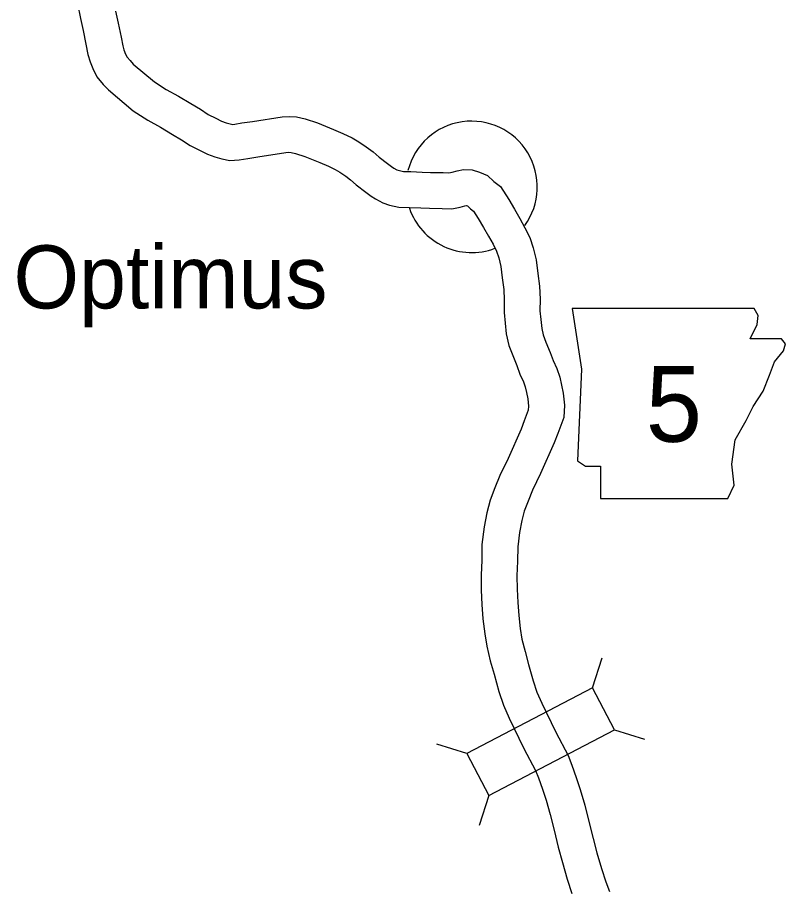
# Model space of a CAD drawing. Extents: x 1377389 to 1380723, y 1168351 to 1170484.
# Drawn here: x 1377801 to 1377865.3, y 1169750.4 to 1169823.5 of the extents above; entities that cross this region are included whole.
import ezdxf

# ---------------------------------------------------------------- set-up
doc = ezdxf.new("R2010")
doc.units = 0
doc.layers.add('B_Fill', color=7, linetype='Continuous')

msp = doc.modelspace()

# ---------------------------------------------------------------- linework, layer by layer
at = {"layer": 'B_Fill'}
for p, q in [((1377849.177, 1169767.377), (1377849.967, 1169769.896)), ((1377851.012, 1169763.868), (1377853.531, 1169763.078)), ((1377838.649, 1169761.873), (1377836.13, 1169762.662)), ((1377840.484, 1169758.364), (1377839.694, 1169755.844))]:
    msp.add_line(p, q, dxfattribs=at)
for points in [[(1377806.068, 1169824.632), (1377806.316, 1169823.399), (1377806.537, 1169822.396), (1377806.758, 1169821.254), (1377806.931, 1169820.376), (1377807.123, 1169819.753), (1377807.343, 1169819.207), (1377807.669, 1169818.514), (1377808.216, 1169817.882), (1377808.644, 1169817.41), (1377810.726, 1169815.654), (1377811.953, 1169814.879), (1377813.004, 1169814.289), (1377814.018, 1169813.684), (1377814.762, 1169813.251), (1377815.491, 1169812.757), (1377816.326, 1169812.337), (1377816.95, 1169812.047), (1377817.571, 1169811.808), (1377818.15, 1169811.657), (1377818.801, 1169811.519), (1377819.591, 1169811.551), (1377820.307, 1169811.689), (1377821.16, 1169811.814), (1377823.501, 1169812.182), (1377823.729, 1169812.193), (1377823.951, 1169812.176), (1377824.306, 1169812.096), (1377825.104, 1169811.834), (1377826.334, 1169811.33), (1377827.058, 1169811.029), (1377827.631, 1169810.76), (1377828.014, 1169810.527), (1377828.517, 1169810.194), (1377828.923, 1169809.894), (1377829.399, 1169809.475), (1377830.208, 1169808.845), (1377830.636, 1169808.535), (1377831.008, 1169808.293), (1377831.61, 1169807.973), (1377832.189, 1169807.778), (1377832.965, 1169807.597), (1377833.864, 1169807.579)], [(1377809.252, 1169824.017), (1377809.475, 1169823.004), (1377809.703, 1169821.829), (1377809.844, 1169821.109), (1377809.953, 1169820.756), (1377810.093, 1169820.407), (1377810.207, 1169820.166), (1377810.461, 1169819.872), (1377810.731, 1169819.575), (1377812.503, 1169818.08), (1377813.49, 1169817.457), (1377814.507, 1169816.886), (1377815.542, 1169816.269), (1377816.359, 1169815.792), (1377817.011, 1169815.351), (1377817.634, 1169815.038), (1377818.124, 1169814.81), (1377818.492, 1169814.668), (1377818.839, 1169814.577), (1377819.054, 1169814.532), (1377819.244, 1169814.54), (1377819.805, 1169814.648), (1377820.71, 1169814.78), (1377823.199, 1169815.172), (1377823.773, 1169815.198), (1377824.393, 1169815.151), (1377825.105, 1169814.992), (1377826.143, 1169814.65), (1377827.479, 1169814.103), (1377828.27, 1169813.773), (1377829.053, 1169813.407), (1377829.624, 1169813.059), (1377830.238, 1169812.652), (1377830.809, 1169812.23), (1377831.313, 1169811.787), (1377832.011, 1169811.244), (1377832.335, 1169811.008), (1377832.532, 1169810.88), (1377832.801, 1169810.737), (1377833.01, 1169810.667), (1377833.34, 1169810.59), (1377833.924, 1169810.578)], [(1377833.957, 1169810.577), (1377834.915, 1169810.537), (1377835.601, 1169810.512), (1377836.657, 1169810.503), (1377837.15, 1169810.483), (1377837.43, 1169810.54), (1377837.833, 1169810.64), (1377838.377, 1169810.747), (1377839.106, 1169810.722), (1377839.708, 1169810.54), (1377840.382, 1169810.259), (1377840.917, 1169809.744), (1377841.46, 1169809.32)], [(1377841.46, 1169809.32), (1377842.161, 1169808.249), (1377842.649, 1169807.423), (1377843.096, 1169806.643), (1377843.514, 1169805.876), (1377843.911, 1169805.051), (1377844.205, 1169804.197), (1377844.448, 1169803.191), (1377844.592, 1169802.062), (1377844.732, 1169800.98), (1377844.776, 1169799.906), (1377844.768, 1169798.94), (1377844.846, 1169798.195), (1377844.915, 1169797.455), (1377845.032, 1169796.907), (1377845.275, 1169796.314), (1377845.633, 1169795.427), (1377845.875, 1169794.77), (1377846.179, 1169794.09), (1377846.429, 1169793.389), (1377846.58, 1169792.697), (1377846.715, 1169792.028), (1377846.82, 1169791.038), (1377846.762, 1169790.009), (1377846.267, 1169788.666), (1377845.972, 1169787.888), (1377844.823, 1169785.316), (1377844.146, 1169783.909), (1377843.771, 1169783.005), (1377843.459, 1169782.174), (1377843.257, 1169781.372), (1377843.06, 1169780.386), (1377842.917, 1169779.183), (1377842.898, 1169777.976), (1377842.848, 1169776.754), (1377842.863, 1169775.642), (1377842.908, 1169774.525), (1377842.99, 1169773.432), (1377843.119, 1169772.33), (1377843.264, 1169771.454), (1377843.52, 1169770.406), (1377843.82, 1169769.322), (1377844.191, 1169767.966), (1377844.52, 1169767.014), (1377844.915, 1169766.1), (1377846.11, 1169763.661), (1377847.125, 1169761.718), (1377847.447, 1169760.917), (1377847.814, 1169759.883), (1377848.148, 1169758.879), (1377848.535, 1169757.548), (1377848.864, 1169756.195), (1377849.215, 1169754.778), (1377849.535, 1169753.577), (1377849.926, 1169752.247), (1377850.289, 1169751.148), (1377850.581, 1169750.335)], [(1377833.831, 1169807.58), (1377834.798, 1169807.539), (1377835.535, 1169807.512), (1377836.583, 1169807.504), (1377837.393, 1169807.47), (1377838.091, 1169807.613), (1377838.484, 1169807.71), (1377838.615, 1169807.736), (1377838.695, 1169807.712), (1377838.708, 1169807.707), (1377838.949, 1169807.475), (1377839.219, 1169807.264)], [(1377839.222, 1169807.261), (1377839.613, 1169806.664), (1377840.055, 1169805.915), (1377840.477, 1169805.179), (1377840.844, 1169804.506), (1377841.132, 1169803.909), (1377841.322, 1169803.355), (1377841.493, 1169802.648), (1377841.616, 1169801.68), (1377841.74, 1169800.725), (1377841.776, 1169799.856), (1377841.767, 1169798.796), (1377841.861, 1169797.901), (1377841.944, 1169797.002), (1377842.155, 1169796.016), (1377842.496, 1169795.183), (1377842.833, 1169794.348), (1377843.095, 1169793.637), (1377843.393, 1169792.972), (1377843.538, 1169792.562), (1377843.644, 1169792.08), (1377843.746, 1169791.572), (1377843.811, 1169790.963), (1377843.792, 1169790.626), (1377843.457, 1169789.717), (1377843.197, 1169789.033), (1377842.101, 1169786.578), (1377841.406, 1169785.134), (1377840.981, 1169784.107), (1377840.591, 1169783.07), (1377840.33, 1169782.033), (1377840.094, 1169780.858), (1377839.92, 1169779.384), (1377839.899, 1169778.062), (1377839.847, 1169776.794), (1377839.864, 1169775.56), (1377839.912, 1169774.353), (1377840.003, 1169773.146), (1377840.147, 1169771.91), (1377840.323, 1169770.851), (1377840.617, 1169769.649), (1377840.927, 1169768.526), (1377841.324, 1169767.079), (1377841.721, 1169765.928), (1377842.19, 1169764.844), (1377843.433, 1169762.306), (1377844.397, 1169760.461), (1377844.64, 1169759.857), (1377844.976, 1169758.908), (1377845.283, 1169757.986), (1377845.636, 1169756.774), (1377845.95, 1169755.48), (1377846.309, 1169754.031), (1377846.647, 1169752.767), (1377847.062, 1169751.354), (1377847.452, 1169750.17)]]:
    msp.add_lwpolyline(points, dxfattribs=at)
for points in [[(1377847.479, 1169799.134), (1377848.241, 1169794.059), (1377847.902, 1169786.361), (1377848.579, 1169785.938), (1377849.848, 1169785.938), (1377849.848, 1169783.231), (1377860.506, 1169783.231), (1377861.014, 1169784.331), (1377860.845, 1169786.107), (1377861.098, 1169788.138), (1377862.029, 1169789.745), (1377862.621, 1169790.929), (1377863.467, 1169792.198), (1377863.974, 1169793.551), (1377864.397, 1169794.651), (1377865.159, 1169795.582), (1377865.328, 1169796.174), (1377864.989, 1169796.597), (1377862.367, 1169796.597), (1377862.959, 1169797.781), (1377863.044, 1169798.542), (1377862.693, 1169799.127)], [(1377840.484, 1169758.364), (1377851.012, 1169763.868), (1377849.177, 1169767.377), (1377838.649, 1169761.873)]]:
    msp.add_lwpolyline(points, close=True, dxfattribs=at)
for start, end in [(323.91026, 165.51389), (198.96543, 290.77226)]:
    msp.add_arc((1377839.05, 1169809.302), 5.5, start, end, dxfattribs=at)

# ---------------------------------------------------------------- texts
for s, height, p in [('Optimus', 5.28, (1377800.702, 1169799.127)), ('5', 6.336, (1377853.626, 1169787.969))]:
    msp.add_text(s, height=height, dxfattribs=at).set_placement(p)

doc.saveas('drawing.dxf')
